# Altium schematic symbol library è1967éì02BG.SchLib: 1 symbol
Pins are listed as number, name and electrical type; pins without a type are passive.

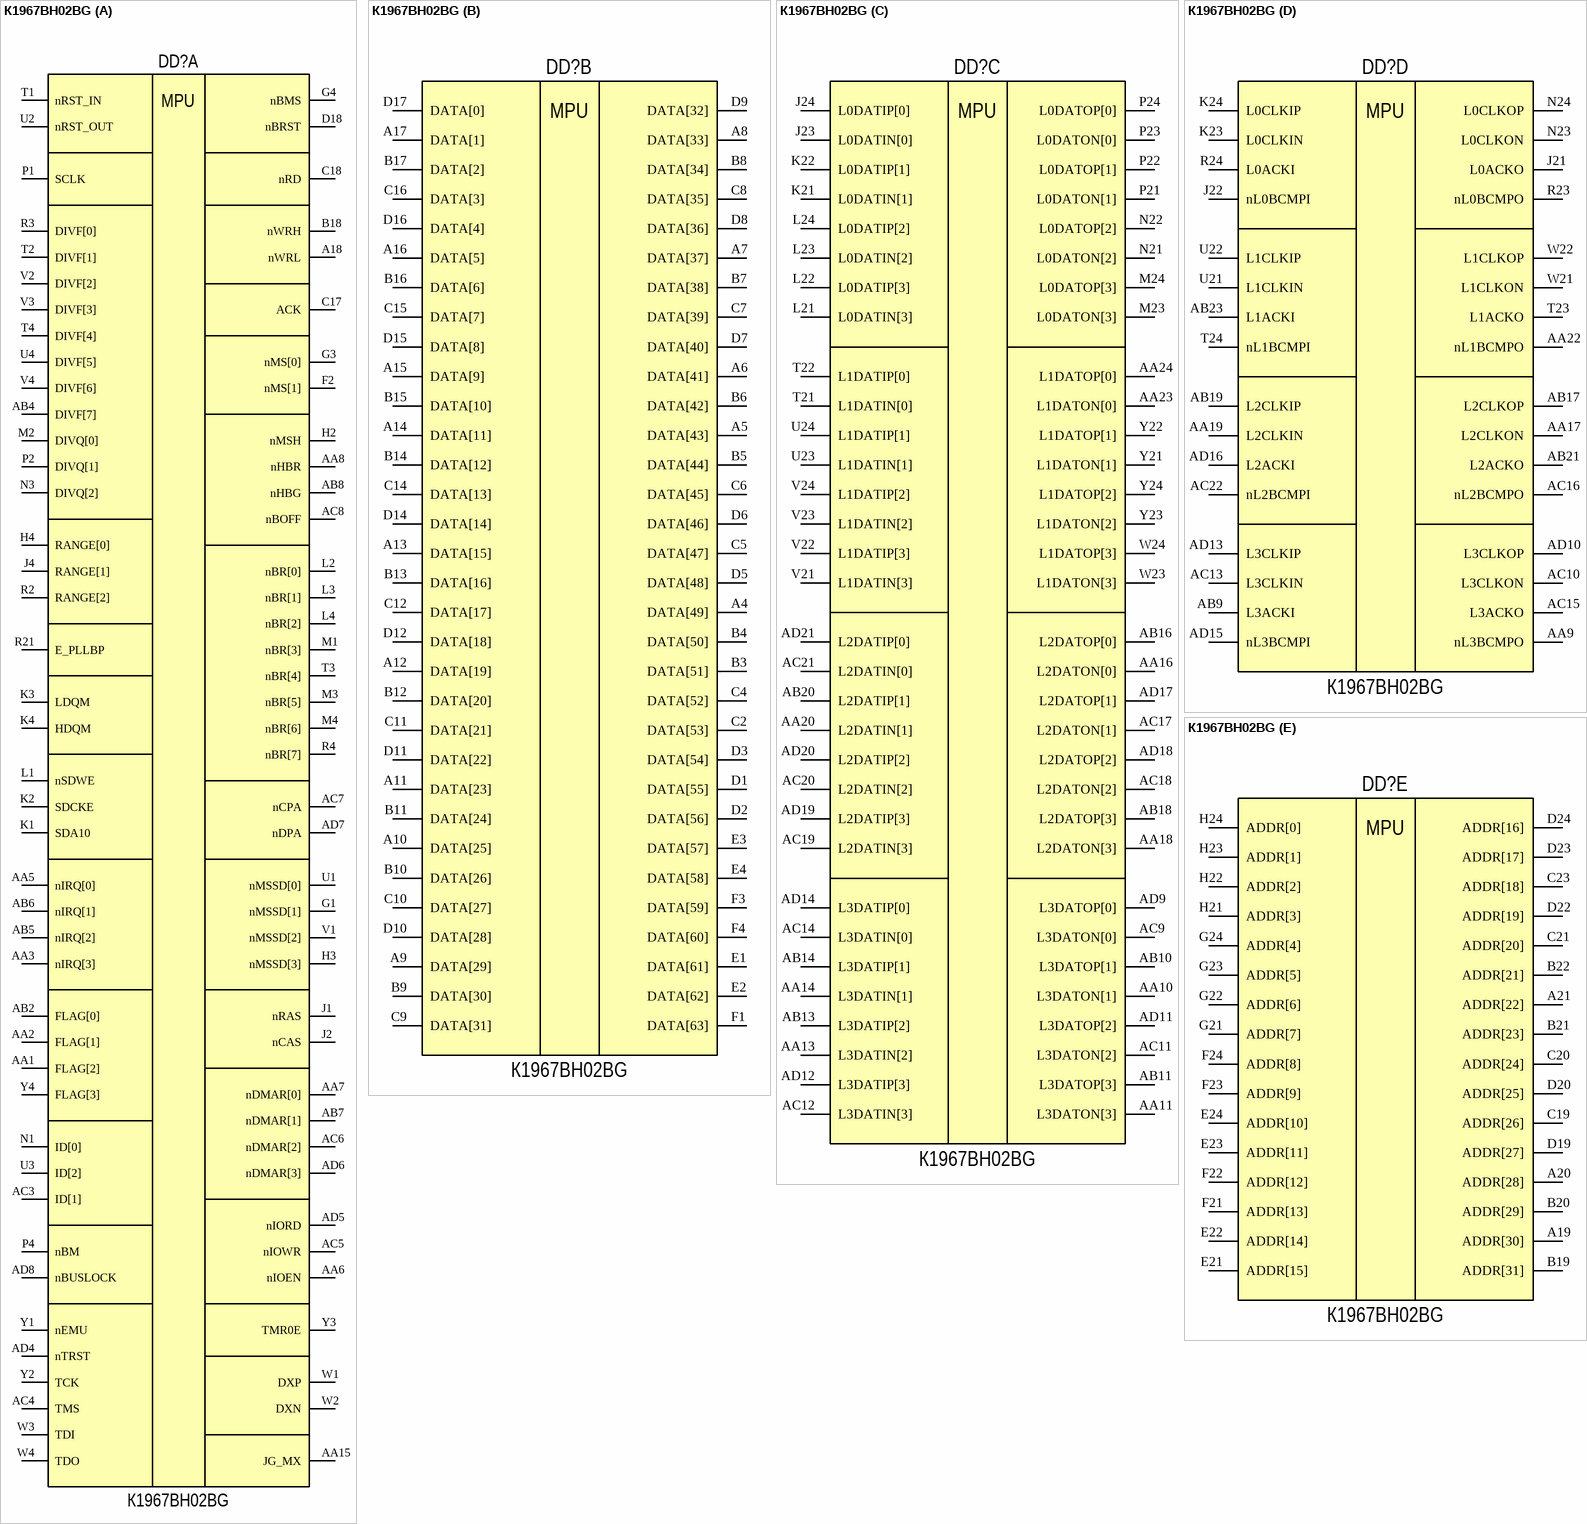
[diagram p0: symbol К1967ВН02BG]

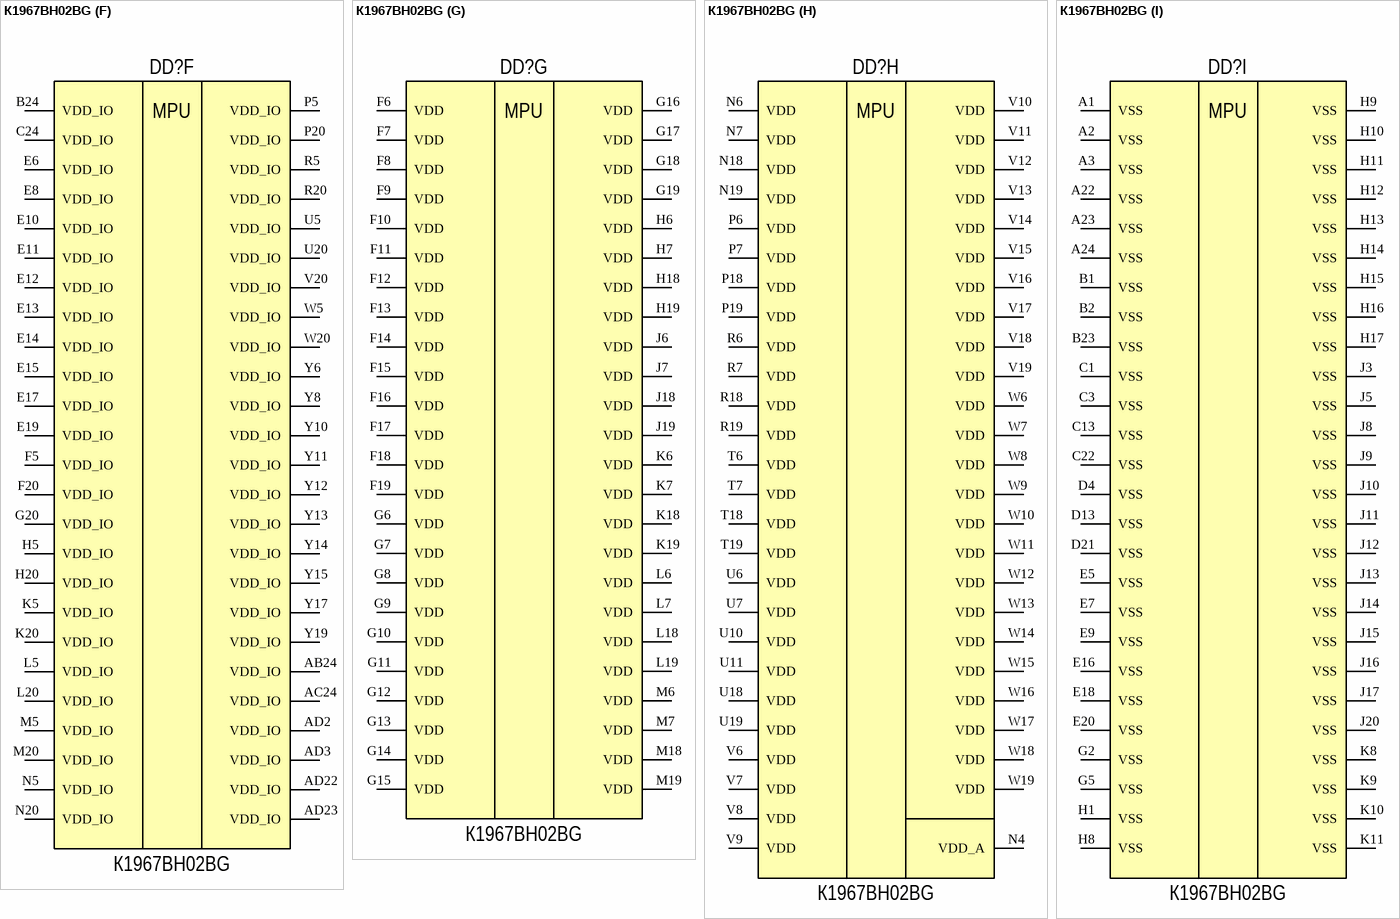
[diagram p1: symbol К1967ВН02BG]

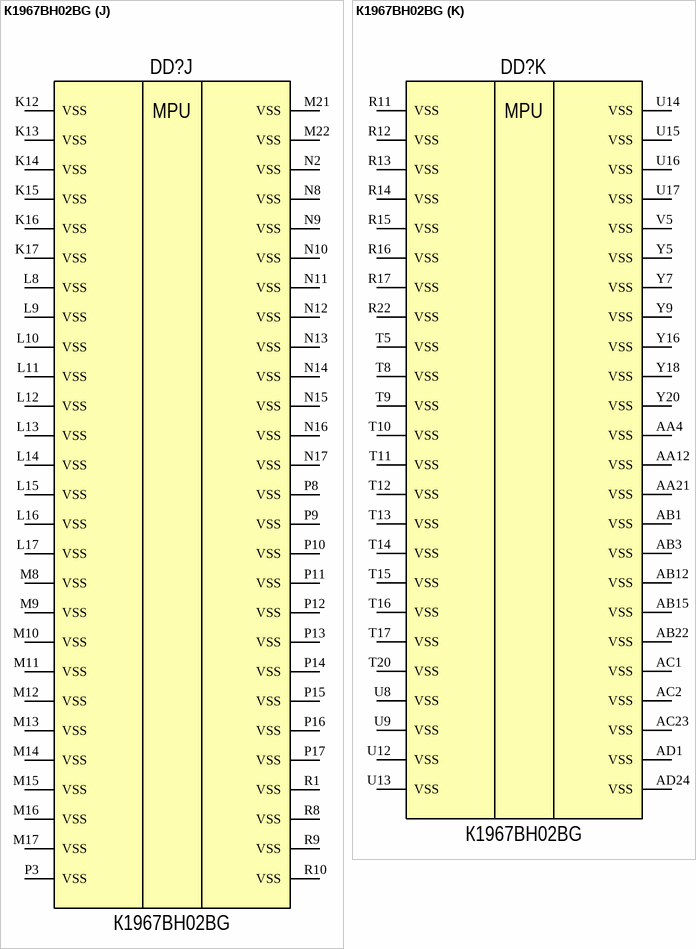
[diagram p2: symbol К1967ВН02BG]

## К1967ВН02BG
designator DD?
part A pins: A18 nWRL, AA1 FLAG[2], AA2 FLAG[1], AA3 nIRQ[3], AA5 nIRQ[0], AA6 nIOEN, AA7 nDMAR[0], AA8 nHBR, AA15 JG_MX, AB2 FLAG[0], AB4 DIVF[7], AB5 nIRQ[2], AB6 nIRQ[1], AB7 nDMAR[1], AB8 nHBG, AC3 ID[1], AC4 TMS, AC5 nIOWR, AC6 nDMAR[2], AC7 nCPA, AC8 nBOFF, AD4 nTRST, AD5 nIORD, AD6 nDMAR[3], AD7 nDPA, AD8 nBUSLOCK, B18 nWRH, C17 ACK, C18 nRD, D18 nBRST, F2 nMS[1], G1 nMSSD[1], G3 nMS[0], G4 nBMS, H2 nMSH, H3 nMSSD[3], H4 RANGE[0], J1 nRAS, J2 nCAS, J4 RANGE[1], K1 SDA10, K2 SDCKE, K3 LDQM, K4 HDQM, L1 nSDWE, L2 nBR[0], L3 nBR[1], L4 nBR[2], M1 nBR[3], M2 DIVQ[0], M3 nBR[5], M4 nBR[6], N1 ID[0], N3 DIVQ[2], P1 SCLK, P2 DIVQ[1], P4 nBM, R2 RANGE[2], R3 DIVF[0], R4 nBR[7], R21 E_PLLBP, T1 nRST_IN, T2 DIVF[1], T3 nBR[4], T4 DIVF[4], U1 nMSSD[0], U2 nRST_OUT, U3 ID[2], U4 DIVF[5], V1 nMSSD[2], V2 DIVF[2], V3 DIVF[3], V4 DIVF[6], W1 DXP, W2 DXN, W3 TDI, W4 TDO, Y1 nEMU, Y2 TCK, Y3 TMR0E, Y4 FLAG[3]
part B pins: A4 DATA[49], A5 DATA[43], A6 DATA[41], A7 DATA[37], A8 DATA[33], A9 DATA[29], A10 DATA[25], A11 DATA[23], A12 DATA[19], A13 DATA[15], A14 DATA[11], A15 DATA[9], A16 DATA[5], A17 DATA[1], B3 DATA[51], B4 DATA[50], B5 DATA[44], B6 DATA[42], B7 DATA[38], B8 DATA[34], B9 DATA[30], B10 DATA[26], B11 DATA[24], B12 DATA[20], B13 DATA[16], B14 DATA[12], B15 DATA[10], B16 DATA[6], B17 DATA[2], C2 DATA[53], C4 DATA[52], C5 DATA[47], C6 DATA[45], C7 DATA[39], C8 DATA[35], C9 DATA[31], C10 DATA[27], C11 DATA[21], C12 DATA[17], C14 DATA[13], C15 DATA[7], C16 DATA[3], D1 DATA[55], D2 DATA[56], D3 DATA[54], D5 DATA[48], D6 DATA[46], D7 DATA[40], D8 DATA[36], D9 DATA[32], D10 DATA[28], D11 DATA[22], D12 DATA[18], D14 DATA[14], D15 DATA[8], D16 DATA[4], D17 DATA[0], E1 DATA[61], E2 DATA[62], E3 DATA[57], E4 DATA[58], F1 DATA[63], F3 DATA[59], F4 DATA[60]
part C pins: AA10 L3DATON[1], AA11 L3DATON[3], AA13 L3DATIN[2], AA14 L3DATIN[1], AA16 L2DATON[0], AA18 L2DATON[3], AA20 L2DATIN[1], AA23 L1DATON[0], AA24 L1DATOP[0], AB10 L3DATOP[1], AB11 L3DATOP[3], AB13 L3DATIP[2], AB14 L3DATIP[1], AB16 L2DATOP[0], AB18 L2DATOP[3], AB20 L2DATIP[1], AC9 L3DATON[0], AC11 L3DATON[2], AC12 L3DATIN[3], AC14 L3DATIN[0], AC17 L2DATON[1], AC18 L2DATON[2], AC19 L2DATIN[3], AC20 L2DATIN[2], AC21 L2DATIN[0], AD9 L3DATOP[0], AD11 L3DATOP[2], AD12 L3DATIP[3], AD14 L3DATIP[0], AD17 L2DATOP[1], AD18 L2DATOP[2], AD19 L2DATIP[3], AD20 L2DATIP[2], AD21 L2DATIP[0], J23 L0DATIN[0], J24 L0DATIP[0], K21 L0DATIN[1], K22 L0DATIP[1], L21 L0DATIN[3], L22 L0DATIP[3], L23 L0DATIN[2], L24 L0DATIP[2], M23 L0DATON[3], M24 L0DATOP[3], N21 L0DATON[2], N22 L0DATOP[2], P21 L0DATON[1], P22 L0DATOP[1], P23 L0DATON[0], P24 L0DATOP[0], T21 L1DATIN[0], T22 L1DATIP[0], U23 L1DATIN[1], U24 L1DATIP[1], V21 L1DATIN[3], V22 L1DATIP[3], V23 L1DATIN[2], V24 L1DATIP[2], W23 L1DATON[3], W24 L1DATOP[3], Y21 L1DATON[1], Y22 L1DATOP[1], Y23 L1DATON[2], Y24 L1DATOP[2]
part D pins: AA9 nL3BCMPO, AA17 L2CLKON, AA19 L2CLKIN, AA22 nL1BCMPO, AB9 L3ACKI, AB17 L2CLKOP, AB19 L2CLKIP, AB21 L2ACKO, AB23 L1ACKI, AC10 L3CLKON, AC13 L3CLKIN, AC15 L3ACKO, AC16 nL2BCMPO, AC22 nL2BCMPI, AD10 L3CLKOP, AD13 L3CLKIP, AD15 nL3BCMPI, AD16 L2ACKI, J21 L0ACKO, J22 nL0BCMPI, K23 L0CLKIN, K24 L0CLKIP, N23 L0CLKON, N24 L0CLKOP, R23 nL0BCMPO, R24 L0ACKI, T23 L1ACKO, T24 nL1BCMPI, U21 L1CLKIN, U22 L1CLKIP, W21 L1CLKON, W22 L1CLKOP
part E pins: A19 ADDR[30], A20 ADDR[28], A21 ADDR[22], B19 ADDR[31], B20 ADDR[29], B21 ADDR[23], B22 ADDR[21], C19 ADDR[26], C20 ADDR[24], C21 ADDR[20], C23 ADDR[18], D19 ADDR[27], D20 ADDR[25], D22 ADDR[19], D23 ADDR[17], D24 ADDR[16], E21 ADDR[15], E22 ADDR[14], E23 ADDR[11], E24 ADDR[10], F21 ADDR[13], F22 ADDR[12], F23 ADDR[9], F24 ADDR[8], G21 ADDR[7], G22 ADDR[6], G23 ADDR[5], G24 ADDR[4], H21 ADDR[3], H22 ADDR[2], H23 ADDR[1], H24 ADDR[0]
part F pins: AB24 VDD_IO (power), AC24 VDD_IO (power), AD2 VDD_IO (power), AD3 VDD_IO (power), AD22 VDD_IO (power), AD23 VDD_IO (power), B24 VDD_IO (power), C24 VDD_IO (power), E6 VDD_IO (power), E8 VDD_IO (power), E10 VDD_IO (power), E11 VDD_IO (power), E12 VDD_IO (power), E13 VDD_IO (power), E14 VDD_IO (power), E15 VDD_IO (power), E17 VDD_IO (power), E19 VDD_IO (power), F5 VDD_IO (power), F20 VDD_IO (power), G20 VDD_IO (power), H5 VDD_IO (power), H20 VDD_IO (power), K5 VDD_IO (power), K20 VDD_IO (power), L5 VDD_IO (power), L20 VDD_IO (power), M5 VDD_IO (power), M20 VDD_IO (power), N5 VDD_IO (power), N20 VDD_IO (power), P5 VDD_IO (power), P20 VDD_IO (power), R5 VDD_IO (power), R20 VDD_IO (power), U5 VDD_IO (power), U20 VDD_IO (power), V20 VDD_IO (power), W5 VDD_IO (power), W20 VDD_IO (power), Y6 VDD_IO (power), Y8 VDD_IO (power), Y10 VDD_IO (power), Y11 VDD_IO (power), Y12 VDD_IO (power), Y13 VDD_IO (power), Y14 VDD_IO (power), Y15 VDD_IO (power), Y17 VDD_IO (power), Y19 VDD_IO (power)
part G pins: F6 VDD (power), F7 VDD (power), F8 VDD (power), F9 VDD (power), F10 VDD (power), F11 VDD (power), F12 VDD (power), F13 VDD (power), F14 VDD (power), F15 VDD (power), F16 VDD (power), F17 VDD (power), F18 VDD (power), F19 VDD (power), G6 VDD (power), G7 VDD (power), G8 VDD (power), G9 VDD (power), G10 VDD (power), G11 VDD (power), G12 VDD (power), G13 VDD (power), G14 VDD (power), G15 VDD (power), G16 VDD (power), G17 VDD (power), G18 VDD (power), G19 VDD (power), H6 VDD (power), H7 VDD (power), H18 VDD (power), H19 VDD (power), J6 VDD (power), J7 VDD (power), J18 VDD (power), J19 VDD (power), K6 VDD (power), K7 VDD (power), K18 VDD (power), K19 VDD (power), L6 VDD (power), L7 VDD (power), L18 VDD (power), L19 VDD (power), M6 VDD (power), M7 VDD (power), M18 VDD (power), M19 VDD (power)
part H pins: N4 VDD_A (power), N6 VDD (power), N7 VDD (power), N18 VDD (power), N19 VDD (power), P6 VDD (power), P7 VDD (power), P18 VDD (power), P19 VDD (power), R6 VDD (power), R7 VDD (power), R18 VDD (power), R19 VDD (power), T6 VDD (power), T7 VDD (power), T18 VDD (power), T19 VDD (power), U6 VDD (power), U7 VDD (power), U10 VDD (power), U11 VDD (power), U18 VDD (power), U19 VDD (power), V6 VDD (power), V7 VDD (power), V8 VDD (power), V9 VDD (power), V10 VDD (power), V11 VDD (power), V12 VDD (power), V13 VDD (power), V14 VDD (power), V15 VDD (power), V16 VDD (power), V17 VDD (power), V18 VDD (power), V19 VDD (power), W6 VDD (power), W7 VDD (power), W8 VDD (power), W9 VDD (power), W10 VDD (power), W11 VDD (power), W12 VDD (power), W13 VDD (power), W14 VDD (power), W15 VDD (power), W16 VDD (power), W17 VDD (power), W18 VDD (power), W19 VDD (power)
part I pins: A1 VSS (power), A2 VSS (power), A3 VSS (power), A22 VSS (power), A23 VSS (power), A24 VSS (power), B1 VSS (power), B2 VSS (power), B23 VSS (power), C1 VSS (power), C3 VSS (power), C13 VSS (power), C22 VSS (power), D4 VSS (power), D13 VSS (power), D21 VSS (power), E5 VSS (power), E7 VSS (power), E9 VSS (power), E16 VSS (power), E18 VSS (power), E20 VSS (power), G2 VSS (power), G5 VSS (power), H1 VSS (power), H8 VSS (power), H9 VSS (power), H10 VSS (power), H11 VSS (power), H12 VSS (power), H13 VSS (power), H14 VSS (power), H15 VSS (power), H16 VSS (power), H17 VSS (power), J3 VSS (power), J5 VSS (power), J8 VSS (power), J9 VSS (power), J10 VSS (power), J11 VSS (power), J12 VSS (power), J13 VSS (power), J14 VSS (power), J15 VSS (power), J16 VSS (power), J17 VSS (power), J20 VSS (power), K8 VSS (power), K9 VSS (power), K10 VSS (power), K11 VSS (power)
part J pins: K12 VSS (power), K13 VSS (power), K14 VSS (power), K15 VSS (power), K16 VSS (power), K17 VSS (power), L8 VSS (power), L9 VSS (power), L10 VSS (power), L11 VSS (power), L12 VSS (power), L13 VSS (power), L14 VSS (power), L15 VSS (power), L16 VSS (power), L17 VSS (power), M8 VSS (power), M9 VSS (power), M10 VSS (power), M11 VSS (power), M12 VSS (power), M13 VSS (power), M14 VSS (power), M15 VSS (power), M16 VSS (power), M17 VSS (power), M21 VSS (power), M22 VSS (power), N2 VSS (power), N8 VSS (power), N9 VSS (power), N10 VSS (power), N11 VSS (power), N12 VSS (power), N13 VSS (power), N14 VSS (power), N15 VSS (power), N16 VSS (power), N17 VSS (power), P3 VSS (power), P8 VSS (power), P9 VSS (power), P10 VSS (power), P11 VSS (power), P12 VSS (power), P13 VSS (power), P14 VSS (power), P15 VSS (power), P16 VSS (power), P17 VSS (power), R1 VSS (power), R8 VSS (power), R9 VSS (power), R10 VSS (power)
part K pins: AA4 VSS (power), AA12 VSS (power), AA21 VSS (power), AB1 VSS (power), AB3 VSS (power), AB12 VSS (power), AB15 VSS (power), AB22 VSS (power), AC1 VSS (power), AC2 VSS (power), AC23 VSS (power), AD1 VSS (power), AD24 VSS (power), R11 VSS (power), R12 VSS (power), R13 VSS (power), R14 VSS (power), R15 VSS (power), R16 VSS (power), R17 VSS (power), R22 VSS (power), T5 VSS (power), T8 VSS (power), T9 VSS (power), T10 VSS (power), T11 VSS (power), T12 VSS (power), T13 VSS (power), T14 VSS (power), T15 VSS (power), T16 VSS (power), T17 VSS (power), T20 VSS (power), U8 VSS (power), U9 VSS (power), U12 VSS (power), U13 VSS (power), U14 VSS (power), U15 VSS (power), U16 VSS (power), U17 VSS (power), V5 VSS (power), Y5 VSS (power), Y7 VSS (power), Y9 VSS (power), Y16 VSS (power), Y18 VSS (power), Y20 VSS (power)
